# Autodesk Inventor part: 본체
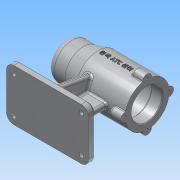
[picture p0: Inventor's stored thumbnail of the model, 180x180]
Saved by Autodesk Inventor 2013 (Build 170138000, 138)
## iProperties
Created: 2019-07
Part Number: 본체
Material: 알루미늄 6061
Document SubType Name: Modeling
Designer: Administrator
Density: 2.71 g/cm^3
Mass: 646.845 g
Surface Area: 655.253 cm^2
Volume: 238.688 cm^3
Author: Administrator
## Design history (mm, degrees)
sketch "스케치1"
  geometry: L1 (56, 30)-(-11, 30); L2 (-11, 30)-(-31, 25); L3 (-31, 25)-(-56, 25); L4 (-56, 25)-(-56, 0); L5 (-56, 0)-(-50, 0); L6 (-50, 0)-(-50, 10.5); L7 (-50, 10.5)-(-47, 10.5); L8 (-47, 10.5)-(-47, 16); L9 (-47, 16)-(-43, 16); L10 (-43, 16)-(-43, 17.5); L11 (-43, 17.5)-(-25, 17.5); L12 (-25, 17.5)-(-25, 21); L13 (-25, 21)-(-13, 21); L14 (-13, 21)-(-13, 24); L15 (-13, 24)-(41, 24); L16 (41, 24)-(41, 21); L17 (41, 21)-(56, 21); L18 (56, 21)-(56, 30); L19 (-56, 0)-(56, 0); 1 further point
  constraints: 38 end point, 11 perpendicular, 6 parallel, 2 midpoint, 1 collinear, 1 horizontal
  dimensions: "d0" = 60 diameter of L1 L19; "d3" = 15 distance of L16.end L17.end; "d4" = 112 distance between parallel lines of L18 L4; "d5" = 54 distance of L14.end L15.end; "d6" = 45 distance from line of L4 L1.end; "d7" = 25 distance from line of L2.end L4; "d8" = 50 diameter of L3 L19; "d9" = 112 distance of L4.end L19.end; "d10" = 4 distance of L8.end L9.end; "d11" = 18 distance of L10.end L11.end; "d12" = 3 distance of L6.end L7.end; "d13" = 12 distance of L12.end L13.end; "d14" = 32 diameter of L9 L19; "d15" = 21 diameter of L7 L19; "d16" = 35 diameter of L11 L19; "d17" = 42 diameter of L13 L19; "d18" = 48 diameter of L15 L19; "d19" = 42 diameter of L17 L19
revolve "회전1" sketch "스케치1" stored, may be unused: angle "d20" = 90 deg
node "작업 평면1"
sketch "스케치2"
  geometry: L1 (56, -35)-(-56, -35); L2 (-56, -35)-(-56, 35); L3 (-56, 35)-(56, 35); L4 (56, 35)-(56, -35); L5 (56, -35)-(-56, 35); L6 (-56, -35)-(56, 35); 1 further point
  constraints: 12 end point, 2 midpoint, 2 parallel, 1 horizontal, 1 perpendicular
  dimensions: "d22" = 112 distance of L2.end L3.end; "d23" = 70 distance of L1.end L2.end
extrude "돌출1" join sketch "스케치2" distance "d24" = 10; taper "d25" = 0 deg
fillet "모깎기1" dims "d26" = 10, "d27" = 0.3, "d28" = 3
sketch "스케치3"
  geometry: C1 r 21 at (0, 0) reference; C2 r 6 at (0, 30); 1 further point
  constraints: 2 vertical alignment, 1 centre point, 1 other
  dimensions: "d29" = 12 diameter of C2
extrude "돌출2" join sketch "스케치3" distance "d32" = 16; taper "d33" = 0 deg
hole "구멍1" diameter "d36" = 3.242; stored, may be unused: countersink angle "d40" = 90 deg, drill point angle "d42" = 118 deg; dims "d34" = 10, "d35" = 10, "d37" = 8, "d38" = 4, "d39" = 2, "d41" = 11
sketch "스케치4"
  geometry: L1 (-19.257, -24)-(31, -24); L2 (31, -24)-(31, -70); L3 (31, -70)-(-36, -70); L4 (-36, -70)-(-19.257, -24); L5 (46, -70)-(-46, -70) reference; L6 (38, -24)-(-10, -24) reference; L7 (-56, -70)-(-46, -70) reference; L8 (-56, -80)-(-56, -70) reference; L9 (56, -70)-(56, -80) reference; 1 further point
  constraints: 8 end point, 2 collinear, 1 horizontal, 1 parallel, 1 perpendicular
  dimensions: "d46" = 110 deg angle of L7 L4; "d47" = 20 distance from line of L3.end L8; "d48" = 25 distance between parallel lines of L9 L2
extrude "돌출3" join sketch "스케치4" stored distance "d49" = 8; taper "d50" = 0 deg
sketch "스케치5"
  geometry: L1 (-22.666, 19.654)-(-70, 28); L2 (-70, 28)-(-70, -28); L3 (-70, -28)-(-22.666, -19.654); L4 (-70, -25)-(-70, -35) reference; L5 (-70, 35)-(-70, 25) reference; L6 (-70, -25)-(-70, 25) reference; L7 (-80, 35)-(-70, 35) reference; L8 (-70, -35)-(-80, -35) reference; A1 r 30 centre (0, 0) between (-29.732, -4) and (-29.732, 4) reference; A2 r 30 centre (0, 0) between (-22.666, 19.654) and (-22.666, -19.654); 1 further point
  constraints: 6 end point, 4 point on circle, 1 centre point, 1 coincident, 1 collinear, 1 vertical
  dimensions: "d51" = 100 deg angle of L3 L4; "d52" = 100 deg angle of L1 L5; "d53" = 7 distance from line of L1.end L7; "d54" = 7 distance from line of L8 L2.end
extrude "돌출4" join sketch "스케치5" stored distance "d55" = 8; taper "d56" = 0 deg
sketch "스케치6" dims "d36" = 3.242, "d38" = 4, "d39" = 2, "d41" = 11
  geometry: C1 r 3 at (-46, 25); C2 r 3 at (-46, -25); 1 further point
  constraints: 2 centre point, 1 vertical alignment
  dimensions: "d57" = 25 vertical distance of point (0, 0) C1.centre; "d58" = 50 distance of C1.centre C2.centre; "d59" = 46 horizontal distance of C1.centre point (0, 0); "d60" = 6 diameter of C1; "d61" = 6 diameter of C2
extrude "돌출5" cut sketch "스케치6" stored distance "d62" = 8; taper "d63" = 0 deg
chamfer "모따기2" distance "d68" = 3; stored, may be unused: second distance "d69" = 2, angle "d70" = 45 deg
chamfer "모따기3" distance "d71" = 1; stored, may be unused: second distance "d72" = 2, angle "d73" = 45 deg
fillet "모깎기3" dims "d74" = 3
fillet "모깎기4" dims "d75" = 1
fillet "모깎기5" dims "d76" = 3
fillet "모깎기6" dims "d77" = 3
fillet "모깎기7" dims "d78" = 3
fillet "모깎기8" dims "d79" = 3
node "작업 평면2"
sketch "스케치7"
  geometry: L1 (56, 6.771)-(56, 29.226) reference; 2 further points
  constraints: 1 horizontal alignment, 1 other
  dimensions: "d81" = 42 distance from line of L1 point (14, 0)
feature "엠보싱1" sketch "스케치7" dims "d0" = 60, "d3" = 15, "d4" = 112, "d5" = 54, "d6" = 45, "d7" = 25, "d8" = 50, "d9" = 112, "d10" = 4, "d11" = 18, "d12" = 3, "d13" = 12, "d14" = 32, "d15" = 21, "d16" = 35, "d17" = 42, "d18" = 48, "d19" = 42, "d82" = 1, "d83" = 0
node "솔리드1"
pattern_circular "원형 패턴1" dims angle "d44" = 360 deg
mirror "대칭1"
other parameters: "d80" = 30.5
